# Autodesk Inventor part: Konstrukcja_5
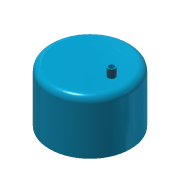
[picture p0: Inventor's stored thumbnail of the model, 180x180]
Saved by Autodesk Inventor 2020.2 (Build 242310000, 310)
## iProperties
Created: 2014-08
Part Number: Konstrukcja_5
Material: Ogólny
Document SubType Name: Modeling
Designer: F.Stasiak
Density: 1 g/cm^3
Appearance: Cyjan
Catalog Web Link: www.expertbooks.pl
Manager: www.cadconsulting.pl
Company: Fabian Stasiak CAD Consulting
Author: F.Stasiak
Subject: Zbiór ćwiczeń. Autodesk Inventor 2020. Kurs Professional
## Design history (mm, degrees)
sketch "Szkic2"
  geometry: C1 r 150 at (0, 0); 2 further points
  constraints: 2 coincident, 1 centre point
  dimensions: "d3" = 300 diameter of C1
extrude "Wyciągnięcie proste1" new body sketch "Szkic2" distance "d6" = 200; taper "d7" = 0 deg
fillet "Zaokrąglenie1" dims "d8" = 24
sketch "Szkic3"
  geometry: C1 r 13.22 at (80, 0); C2 r 126 at (0, 0) reference; 1 further point
  constraints: 1 centre point, 1 horizontal alignment
  dimensions: "d9" = 26.441 diameter of C1; "d19" = 80 distance of C1.centre point (0, 0)
extrude "Wyciągnięcie proste2" join sketch "Szkic3" distance "d13" = 30; taper "d14" = 0 deg
feature "Gwint2" dims "d17" = 10, "d18" = 0
hole "Otwór1" diameter "d22" = 20; stored, may be unused: countersink angle "d26" = 90 deg, drill point angle "d28" = 118 deg; dims "d20" = 10, "d21" = 10, "d23" = 6, "d24" = 4, "d25" = 2, "d27" = 50
node "Bryła1"
node "Pętla rzutowana1"
